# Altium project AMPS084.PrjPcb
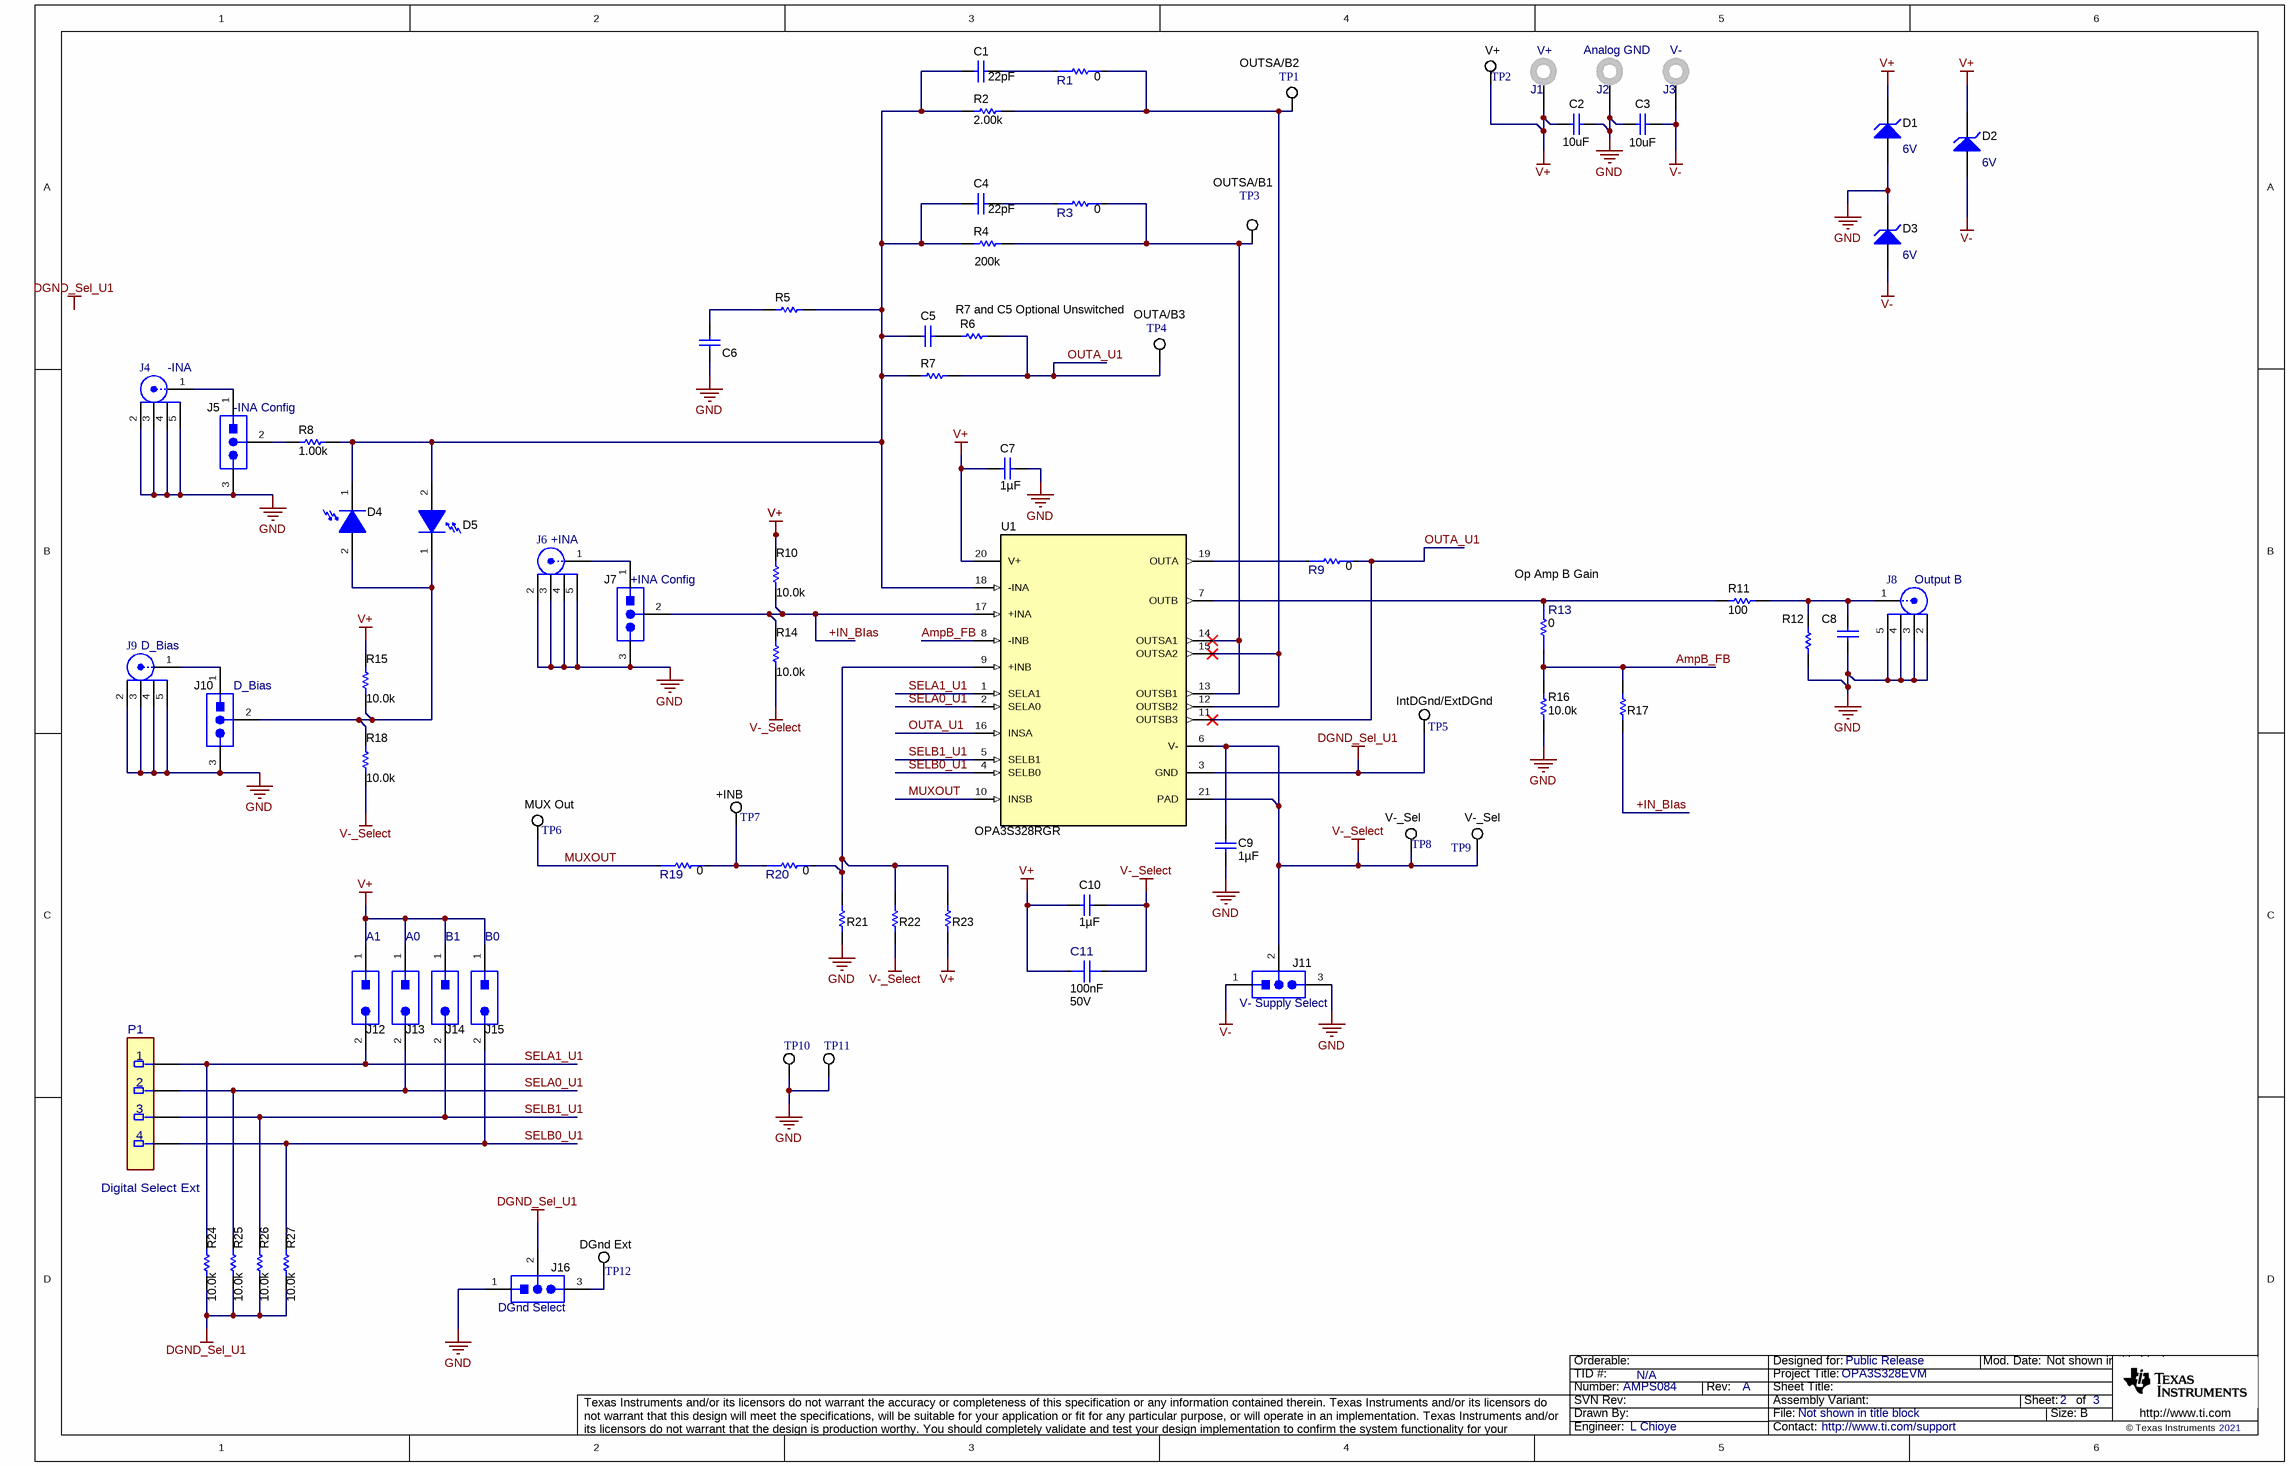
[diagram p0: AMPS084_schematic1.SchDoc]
TID: N/A; TechSupport: http://www.ti.com/support; SCH_Rev: A; PRJ_Title: OPA3S328EVM; PRJ_Number: AMPS084; PRJ_Engineer: L Chioye; PRJ_Customer: Public Release; PCB_Rev: A; PCB_Layout: L Chioye; CopyrightYear: 2021
3 sheets, 183 parts. Net scope: global (net labels, ports and power ports of the same name join across sheets).
Board file: AMPS084.PcbDoc
Sheets:
  AMPS084_schematic1.SchDoc
  AMPS084_schematic2.SchDoc
  AMPS084_Hardware.SchDoc

## Sheet AMPS084_schematic1.SchDoc
size 431 x 279 mm; Date: Not shown in title block; ApprovedBy: Not shown in title block; CheckedBy: Not shown in title block; Author: Not shown in title block; CompanyName: Not shown in title block; Engineer: Not shown in title block; Organization: Not shown in title block; Address1: Not shown in title block; Address2: Not shown in title block; Address3: Not shown in title block; Address4: Not shown in title block; DocumentNumber: 2; Revision: Use project parameter SCH_Rev; SheetNumber: 2; SheetTotal: 3; PageSetup: Record=PageOptions¦CenterHorizontal=True¦CenterVertical=True¦PrintScale=1.00¦XCorrection=1.00¦YCorrection=1.00¦PrintKind=0¦BorderSize=5000000¦LeftOffset=0¦BottomOffset=0¦Orientation=2¦PaperLength=1000¦PaperWidth=1000¦Scale=100¦PaperSource=15¦PrintQuality=600¦MediaType=1¦DitherType=10¦PaperKind=Letter¦PrintScaleMode=1

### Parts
C1  ValueDisplayed: 22pF  [0603]  (hidden comment: 06035A220JAT2A)
C2  ValueDisplayed: 10uF  [1206_190]  (hidden comment: C3216X7R1E106M160AE)
C3  ValueDisplayed: 10uF  [1206_190]  (hidden comment: C3216X7R1E106M160AE)
C4  ValueDisplayed: 22pF  [0603]  (hidden comment: 06035A220JAT2A)
C5  C0603C102J5GACTU  [0603]  (value not drawn)
C6  C0603C102J5GACTU  [0603]  (value not drawn)
C7  Cap_F: 1µF  [0805_HV]  (hidden comment: 08055C105KAT2A)
C8  C1206C104M5RACTU  [1206]  (value not drawn)
C9  Cap_F: 1µF  [0805_HV]  (hidden comment: 08055C105KAT2A)
C10  Cap_F: 1µF  [0805_HV]  (hidden comment: 08055C105KAT2A)
C11  Cap_F: 100nF  VDC_V: 50V  [FP-GCE21BR71H104KA01L_0805-MFG]  (hidden comment: GCE21BR71H104KA01L)
D1  value 6V  [SOD-323]  (hidden comment: MMSZ5233BS-7-F)
D2  value 6V  [SOD-323]  (hidden comment: MMSZ5233BS-7-F)
D3  value 6V  [SOD-323]  (hidden comment: MMSZ5233BS-7-F)
D4  SFH 2701  [SFH_2701]  (value not drawn)
D5  SFH 2701  [SFH_2701]  (value not drawn)
J1  V+  [Keystone_575-4]
J2  Analog GND  [Keystone_575-4]
J3  V-  [Keystone_575-4]
J4  -INA  [TE_5-1814832-1]
J5  -INA Config  [Samtec_TSM-103-01-X-SV]
J6  +INA  [TE_5-1814832-1]
J7  +INA Config  [Samtec_TSM-103-01-X-SV]
J8  Output B  [TE_5-1814832-1]
J9  D_Bias  [TE_5-1814832-1]
J10  D_Bias  [Samtec_TSM-103-01-X-SV]
J11  V- Supply Select  [Samtec_TSM-103-01-X-SV]
J12  A1  [Samtec_TSM-102-01-L-SV]
J13  A0  [Samtec_TSM-102-01-L-SV]
J14  B1  [Samtec_TSM-102-01-L-SV]
J15  B0  [Samtec_TSM-102-01-L-SV]
J16  DGnd Select  [Samtec_TSM-103-01-X-SV]
P1  Digital Select Ext  [FP-TSM-104-01-L-SV-P-TR_HDR4-MFG]
R1  Res_ohm: 0  [FP-ERJ-3GEY0R00V_0603-MFG]  (hidden comment: ERJ-3GEY0R00V)
R2  ValueDisplayed: 2.00k  [0603]  (hidden comment: RG1608P-202-B-T5)
R3  Res_ohm: 0  [FP-ERJ-3GEY0R00V_0603-MFG]  (hidden comment: ERJ-3GEY0R00V)
R4  ValueDisplayed: 200k  [0603]  (hidden comment: RG1608P-204-B-T5)
R5  RG1608P-102-B-T5  [0603]  (value not drawn)
R6  RG1608P-102-B-T5  [0603]  (value not drawn)
R7  RG1608P-102-B-T5  [0603]  (value not drawn)
R8  ValueDisplayed: 1.00k  [0805_HV]  (hidden comment: CRCW08051K00FKEA)
R9  Res_ohm: 0  [FP-ERJ-3GEY0R00V_0603-MFG]  (hidden comment: ERJ-3GEY0R00V)
R10  ValueDisplayed: 10.0k  [0603]  (hidden comment: RCG060310K0FKEA)
R11  ValueDisplayed: 100  [0805_HV]  (hidden comment: CRCW0805100RFKEA)
R12  CRCW120610K0FKEA  [1206]  (value not drawn)
R13  Res_ohm: 0  [FP-ERJ-3GEY0R00V_0603-MFG]  (hidden comment: ERJ-3GEY0R00V)
R14  ValueDisplayed: 10.0k  [0603]  (hidden comment: RCG060310K0FKEA)
R15  ValueDisplayed: 10.0k  [0603]  (hidden comment: RCG060310K0FKEA)
R16  ValueDisplayed: 10.0k  [0603]  (hidden comment: RT0603BRD0710KL)
R17  RG1608P-102-B-T5  [0603]  (value not drawn)
R18  ValueDisplayed: 10.0k  [0603]  (hidden comment: RCG060310K0FKEA)
R19  Res_ohm: 0  [FP-ERJ-3GEY0R00V_0603-MFG]  (hidden comment: ERJ-3GEY0R00V)
R20  Res_ohm: 0  [FP-ERJ-3GEY0R00V_0603-MFG]  (hidden comment: ERJ-3GEY0R00V)
R21  RG1608P-102-B-T5  [0603]  (value not drawn)
R22  RG1608P-102-B-T5  [0603]  (value not drawn)
R23  RG1608P-102-B-T5  [0603]  (value not drawn)
R24  ValueDisplayed: 10.0k  [0603]  (hidden comment: RCG060310K0FKEA)
R25  ValueDisplayed: 10.0k  [0603]  (hidden comment: RCG060310K0FKEA)
R26  ValueDisplayed: 10.0k  [0603]  (hidden comment: RCG060310K0FKEA)
R27  ValueDisplayed: 10.0k  [0603]  (hidden comment: RCG060310K0FKEA)
TP1  OUTSA/B2  [Testpoint_Keystone_Compact]
TP2  V+  [Testpoint_Keystone_Compact]
TP3  OUTSA/B1  [Testpoint_Keystone_Compact]
TP4  OUTA/B3  [Testpoint_Keystone_Compact]
TP5  IntDGnd/ExtDGnd  [Testpoint_Keystone_Compact]
TP6  MUX Out  [Testpoint_Keystone_Compact]
TP7  +INB  [Testpoint_Keystone_Compact]
TP8  V-_Sel  [Testpoint_Keystone_Compact]
TP9  V-_Sel  [Testpoint_Keystone_Compact]
TP10  Analog GND  [Testpoint_Keystone_Compact]  (value not drawn)
TP11  Analog GND  [Testpoint_Keystone_Compact]  (value not drawn)
TP12  DGnd Ext  [Testpoint_Keystone_Compact]
U1  OPA3S328RGR  [RGR0020A]

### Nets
DGND_Sel_U1: J16.2 R24.1 R25.1 R26.1 R27.1 TP5.1 U1.3(GND)
GND: C2.1 C3.2 C6.2 C7.1 C8.1 C9.2 D1.2(A) D3.1(K) J2.1 J4.2 J4.3 J4.4 J4.5 J5.3 J6.2 J6.3 J6.4 J6.5 J7.3 J8.2 J8.3 J8.4 J8.5 J9.2 J9.3 J9.4 J9.5 J10.3 J11.3 J16.1 R12.1 R16.1 R21.1 TP10.1 TP11.1
V+: C2.2 C7.2 C10.2 C11.1 D1.1(K) D2.1(K) J1.1 J12.1 J13.1 J14.1 J15.1 R10.2 R15.2 R23.1 TP2.1 U1.20(V+)
V-: C3.1 D2.2(A) D3.2(A) J3.1 J11.1
V-_Select: C9.1 C10.1 C11.2 J11.2 R14.1 R18.1 R22.1 TP8.1 TP9.1 U1.6(V-) U1.21(PAD)
+IN_BIas: J7.2 R10.1 R14.2 R17.1 U1.17(+INA)
AmpB_FB: R13.1 R16.2 R17.2 U1.8(-INB)
MUXOUT: R19.1 TP6.1 U1.10(INSB)
OUTA_U1: R6.2 R7.2 R9.2 TP4.1 U1.11(OUTSB3) U1.16(INSA)
SELA0_U1: J13.2 P1.2 R25.2 U1.2(SELA0)
SELA1_U1: J12.2 P1.1 R24.2 U1.1(SELA1)
SELB0_U1: J15.2 P1.4 R27.2 U1.4(SELB0)
SELB1_U1: J14.2 P1.3 R26.2 U1.5(SELB1)
NetC1_1: C1.1 R1.1
NetC1_2: C1.2 C4.2 C5.2 D4.1(C) D5.2(A) R2.1 R4.1 R5.2 R7.1 R8.2 U1.18(-INA)
NetC4_1: C4.1 R3.1
NetC5_1: C5.1 R6.1
NetC6_1: C6.1 R5.1
NetC8_2: C8.2 J8.1 R11.2 R12.2
NetD4_2: D4.2(A) D5.1(C) J10.2 R15.1 R18.2
NetJ4_1: J4.1 J5.1
NetJ5_2: J5.2 R8.1
NetJ6_1: J6.1 J7.1
NetJ9_1: J9.1 J10.1
NetJ16_3: J16.3 TP12.1
NetR1_2: R1.2 R2.2 TP1.1 U1.12(OUTSB2) U1.15(OUTSA2)
NetR3_2: R3.2 R4.2 TP3.1 U1.13(OUTSB1) U1.14(OUTSA1)
NetR9_1: R9.1 U1.19(OUTA)
NetR11_1: R11.1 R13.2 U1.7(OUTB)
NetR19_2: R19.2 R20.1 TP7.1
NetR20_2: R20.2 R21.2 R22.2 R23.2 U1.9(+INB)

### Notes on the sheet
- R7 and C5 Optional Unswitched
- (near R13) Op Amp B Gain
- Labels drawn without touching a wire or pin: DGND_Sel_U1

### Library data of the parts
C1 C4 = CMP-0006775-4: CAP, CERM, 22 pF, 50 V, +/- 5%, C0G/NP0, 0603; Manufacturer: AVX; TaMin_C: -55°C; ESR_ohm: 0.259; Polarized: N; SizeAreaWB_mm2: 4.68; Value1: 0.259 ohm; U/M: EA; Value: 22pF; TaMax_C: 125°C; SizeZ_mm: 1; SizeX_mm: 1.6; SizeY_mm: 0.8; Value2: 50V; SizeArea_mm2: 1.28; AEC Category: Q200
C2 C3 = CMP-0008692-1: CAP, CERM, 10 uF, 25 V, +/- 20%, X7R, 1206_190; Manufacturer: TDK; TaMin_C: -55°C; Polarized: N; SizeAreaWB_mm2: 10.92; Value1: Unknown; U/M: EA; Value: 10uF; TaMax_C: 125°C; SizeZ_mm: 1.9; SizeX_mm: 3.2; SizeY_mm: 1.6; Cap_Case: 1206; Value2: 25V; SizeArea_mm2: 5.12; Cap_F: 10µF; AEC Category: Q200
C5 C6 = CMP-0006843-4: CAP, CERM, 1000 pF, 50 V, +/- 5%, C0G/NP0, 0603; Manufacturer: Kemet; TaMin_C: -55°C; Polarized: N; SizeAreaWB_mm2: 4.68; Value1: Unknown; U/M: EA; Value: 1000pF; TaMax_C: 125°C; SizeZ_mm: 1; SizeX_mm: 1.6; SizeY_mm: 0.8; Value2: 50V; SizeArea_mm2: 1.28; Cap_F: 1nF; AEC Category: Q200
C7 C9 C10 = CMP-0007634-2: CAP, CERM, 1 uF, 50 V, +/- 10%, X7R, 0805; Manufacturer: AVX; TaMin_C: -55°C; Polarized: N; SizeAreaWB_mm2: 6.75; Value1: Unknown; U/M: EA; Value: 1uF; TaMax_C: 125°C; SizeZ_mm: 1.45; SizeX_mm: 2; SizeY_mm: 1.25; Cap_Case: 0805; Value2: 50V; SizeArea_mm2: 2.5; AEC Category: Q200
C8 = CMP-0008587-2: CAP, CERM, 0.1 uF, 50 V, +/- 20%, X7R, 1206; Manufacturer: Kemet; TaMin_C: -55°C; ESR_ohm: 0.059; Polarized: N; SizeAreaWB_mm2: 10.92; Value1: 0.059 ohm; U/M: EA; Value: 0.1uF; TaMax_C: 125°C; SizeZ_mm: 1.35; SizeX_mm: 3.2; SizeY_mm: 1.6; Value2: 50V; SizeArea_mm2: 5.12; Cap_F: 100nF; IRMS_A: 1.2A; AEC Category: Q200
C11 = CMP-0088731-1: 0.1µF ±10% 50V Ceramic Capacitor X7R 0805 (2012 Metric); Manufacturer: Murata; SizeZ_mm: 1.45mm; TempCo: 15%; AEC Grade: Grade 1; AEC Qualified: Yes; ValueDisplayed: 0.1uF
D1-D3 = CMP-0005856-3: Diode, Zener, 6 V, 200 mW, SOD-323; Manufacturer: Diodes Inc.; Power_W: 200mW; SizeY_mm: 1.35; SizeArea_mm2: 3.645; AEC Category: Q101; RJA_CperW: 350; SizeZ_mm: 1; Value1: 0.2W; SizeX_mm: 2.7; SizeAreaWB_mm2: 8.695
D4 D5 = CMP-0002013-4: High Speed PIN Photodiode, SMD; Manufacturer: OSRAM; Value: 820nm
J1-J3 = CMP-0055165-1: Standard Banana Jack, Uninsulated, 5.5mm; Manufacturer: Keystone; PartNumber: 575-4; CT: TRUE; Green_REACh: Passed; CNHeader: FALSE; Green_Lifecycle: Active
J4 J6 J8 J9 = CMP-0054990-1: SMA Straight PCB Socket Die Cast, 50 Ohm, TH; Manufacturer: TE Connectivity; PartNumber: 5-1814832-1; CNHeader: FALSE; Green_Lifecycle: Active; Green_REACh: Passed; CT: TRUE
J5 J7 J10 J11 J16 = CMP-0075402-1: Header, 100mil, 3x1, Gold, SMT; PartNumber: TSM-103-01-L-SV; Manufacturer: Samtec; Green_REACh: Passed; CT: False; Green_Lifecycle: Active; CNHeader: True
J12-J15 = CMP-0075467-1: Header, 100mil, 2x1, Gold with Tin Tail, SMT; PartNumber: TSM-102-01-L-SV; Manufacturer: Samtec; Pitch_mm: 2.54; Gender: Male; Cert_CSA: Y; Green_REACh: Passed; Current_A: 5.4A; Voltage_V: 475V; CT: False; Shrouded: N; Green_Lifecycle: Active; Row_Count: 1; CNHeader: True
P1 = CMP-0087359-1: PartNumber: TSM-104-01-L-SV-P-TR; Manufacturer: Samtec; ContactFinish: Gold,Nickel; Current_A: 5.4A; Voltage_V: 475V; Row_Count: 1
R1 R3 R9 R13 R19 R20 = CMP-0089143-1: 0 Ohms Jumper 0.1W, 1/10W Chip Resistor 0603 (1608 Metric) Automotive AEC-Q200 Thick Film; Manufacturer: Panasonic; SizeZ_mm: 0.55mm; AEC Grade: Grade 0; VDC_V: 75V; TempCo: -100/+600ppm/°C; AEC Qualified: Yes; Power_W: 100mW; Tolerance_%: 5%
R2 = CMP-0023463-3: RES, 2.00 k, 0.1%, 0.1 W, 0603; Manufacturer: Susumu Co Ltd; Power_W: 100mW; TempCo: 25 ppm/C; Value_Code: 2k00; U/M: EA; Value: 2.00k; EIA_Code: E192; Res_ohm: 2k; SizeX_mm: 1.6; SizeY_mm: 0.8; SizeZ_mm: 1; Value2: 0.1W; SizeArea_mm2: 1.28; VDC_V: 75V; AEC Category: Q200
R4 = CMP-0023465-3: RES, 200 k, 0.1%, 0.1 W, 0603; Manufacturer: Susumu Co Ltd; Power_W: 100mW; TempCo: 25 ppm/C; U/M: EA; Value: 200k; EIA_Code: E192; SizeX_mm: 1.6; SizeY_mm: 0.8; SizeZ_mm: 1; Value2: 0.1W; SizeArea_mm2: 1.28; VDC_V: 75V; AEC Category: Q200
R5-R7 R17 R21-R23 = CMP-0023403-3: RES, 1.00 k, 0.1%, 0.1 W, 0603; Manufacturer: Susumu Co Ltd; Power_W: 100mW; TempCo: 25 ppm/C; Value_Code: 1k00; U/M: EA; Value: 1.00k; EIA_Code: E192; Res_ohm: 1k; SizeX_mm: 1.6; SizeY_mm: 0.8; SizeZ_mm: 1; Value2: 0.1W; SizeArea_mm2: 1.28; VDC_V: 75V; AEC Category: Q200
R8 = CMP-0020951-3: RES, 1.00 k, 1%, 0.125 W, AEC-Q200 Grade 0, 0805; Manufacturer: Vishay-Dale; Power_W: 125mW; TempCo: 100 ppm/C; Value_Code: 1k00; Value: 1.00k; EIA_Code: E96; Res_ohm: 1k; SizeX_mm: 2; SizeY_mm: 1.25; SizeZ_mm: 1.45; Value2: 0.125W; SizeArea_mm2: 2.5; AEC Qualified: Y; VDC_V: 150V; AEC Category: Q200; AEC Grade: 0
R10 R14 R15 R18 R24-R27 = CMP-0023337-3: RES, 10.0 k, 1%, 0.1 W, 0603; Manufacturer: Vishay Draloric; Power_W: 100mW; TempCo: 100 ppm/C; Value_Code: 10k0; U/M: EA; Value: 10.0k; EIA_Code: E96; Res_ohm: 10k; SizeX_mm: 1.6; SizeY_mm: 0.8; SizeZ_mm: 1; Value2: 0.1W; SizeArea_mm2: 1.28; AEC Qualified: N; VDC_V: 75V; AEC Category: Q200
R11 = CMP-0020835-3: RES, 100, 1%, 0.125 W, AEC-Q200 Grade 0, 0805; Manufacturer: Vishay-Dale; Power_W: 125mW; TempCo: 100 ppm/C; Value_Code: 100R; Value: 100; EIA_Code: E96; SizeX_mm: 2; SizeY_mm: 1.25; SizeZ_mm: 1.45; Value2: 0.125W; SizeArea_mm2: 2.5; AEC Qualified: Y; VDC_V: 150V; AEC Category: Q200; AEC Grade: 0
R12 = CMP-0016577-1: RES, 10.0 k, 1%, 0.25 W, 1206; Manufacturer: Vishay-Dale; Power_W: 250mW; TempCo: 100 ppm/C; Value_Code: 10k0; U/M: EA; Value: 10.0k; EIA_Code: E96; Res_ohm: 10k; SizeX_mm: 3.2; SizeY_mm: 1.6; SizeZ_mm: 1.35; Value2: 0.25W; SizeArea_mm2: 5.12; VDC_V: 200V; AEC Category: Q200
R16 = CMP-0023653-3: RES, 10.0 k, 0.1%, 0.1 W, 0603; Manufacturer: Yageo America; Power_W: 100mW; TempCo: 25 ppm/C; Value_Code: 10k0; U/M: EA; Value: 10.0k; EIA_Code: E192; Res_ohm: 10k; SizeX_mm: 1.6; SizeY_mm: 0.8; SizeZ_mm: 1; Value2: 0.1W; SizeArea_mm2: 1.28; VDC_V: 75V; AEC Category: Q200
TP1-TP12 = CMP-0055153-1: Test Point, Compact, SMT; Manufacturer: Keystone; CNHeader: FALSE; Green_Lifecycle: Active; Green_REACh: Passed; CT: TRUE
U1 = CMP-0860039-1: 40-MHz CMOS Operational Amplifier With Switches, RGR0020A (VQFN-20); Manufacturer: Texas Instruments; SizeArea_mm2: 12.25; CompType: IC; AEC Category: Q200; SizeZ_mm: 1; SizeAreaWB_mm2: 20.25; AEC Qualified: N; SizeX_mm: 3.5

## Sheet AMPS084_schematic2.SchDoc
size 431 x 279 mm; Date: Not shown in title block; ApprovedBy: Not shown in title block; CheckedBy: Not shown in title block; Author: Not shown in title block; CompanyName: Not shown in title block; Engineer: Not shown in title block; Organization: Not shown in title block; Address1: Not shown in title block; Address2: Not shown in title block; Address3: Not shown in title block; Address4: Not shown in title block; DocumentNumber: 2; Revision: Use project parameter SCH_Rev; SheetNumber: 2; SheetTotal: 3; PageSetup: Record=PageOptions¦CenterHorizontal=True¦CenterVertical=True¦PrintScale=1.00¦XCorrection=1.00¦YCorrection=1.00¦PrintKind=0¦BorderSize=5000000¦LeftOffset=0¦BottomOffset=0¦Orientation=2¦PaperLength=1000¦PaperWidth=1000¦Scale=100¦PaperSource=15¦PrintQuality=600¦MediaType=1¦DitherType=10¦PaperKind=Letter¦PrintScaleMode=1
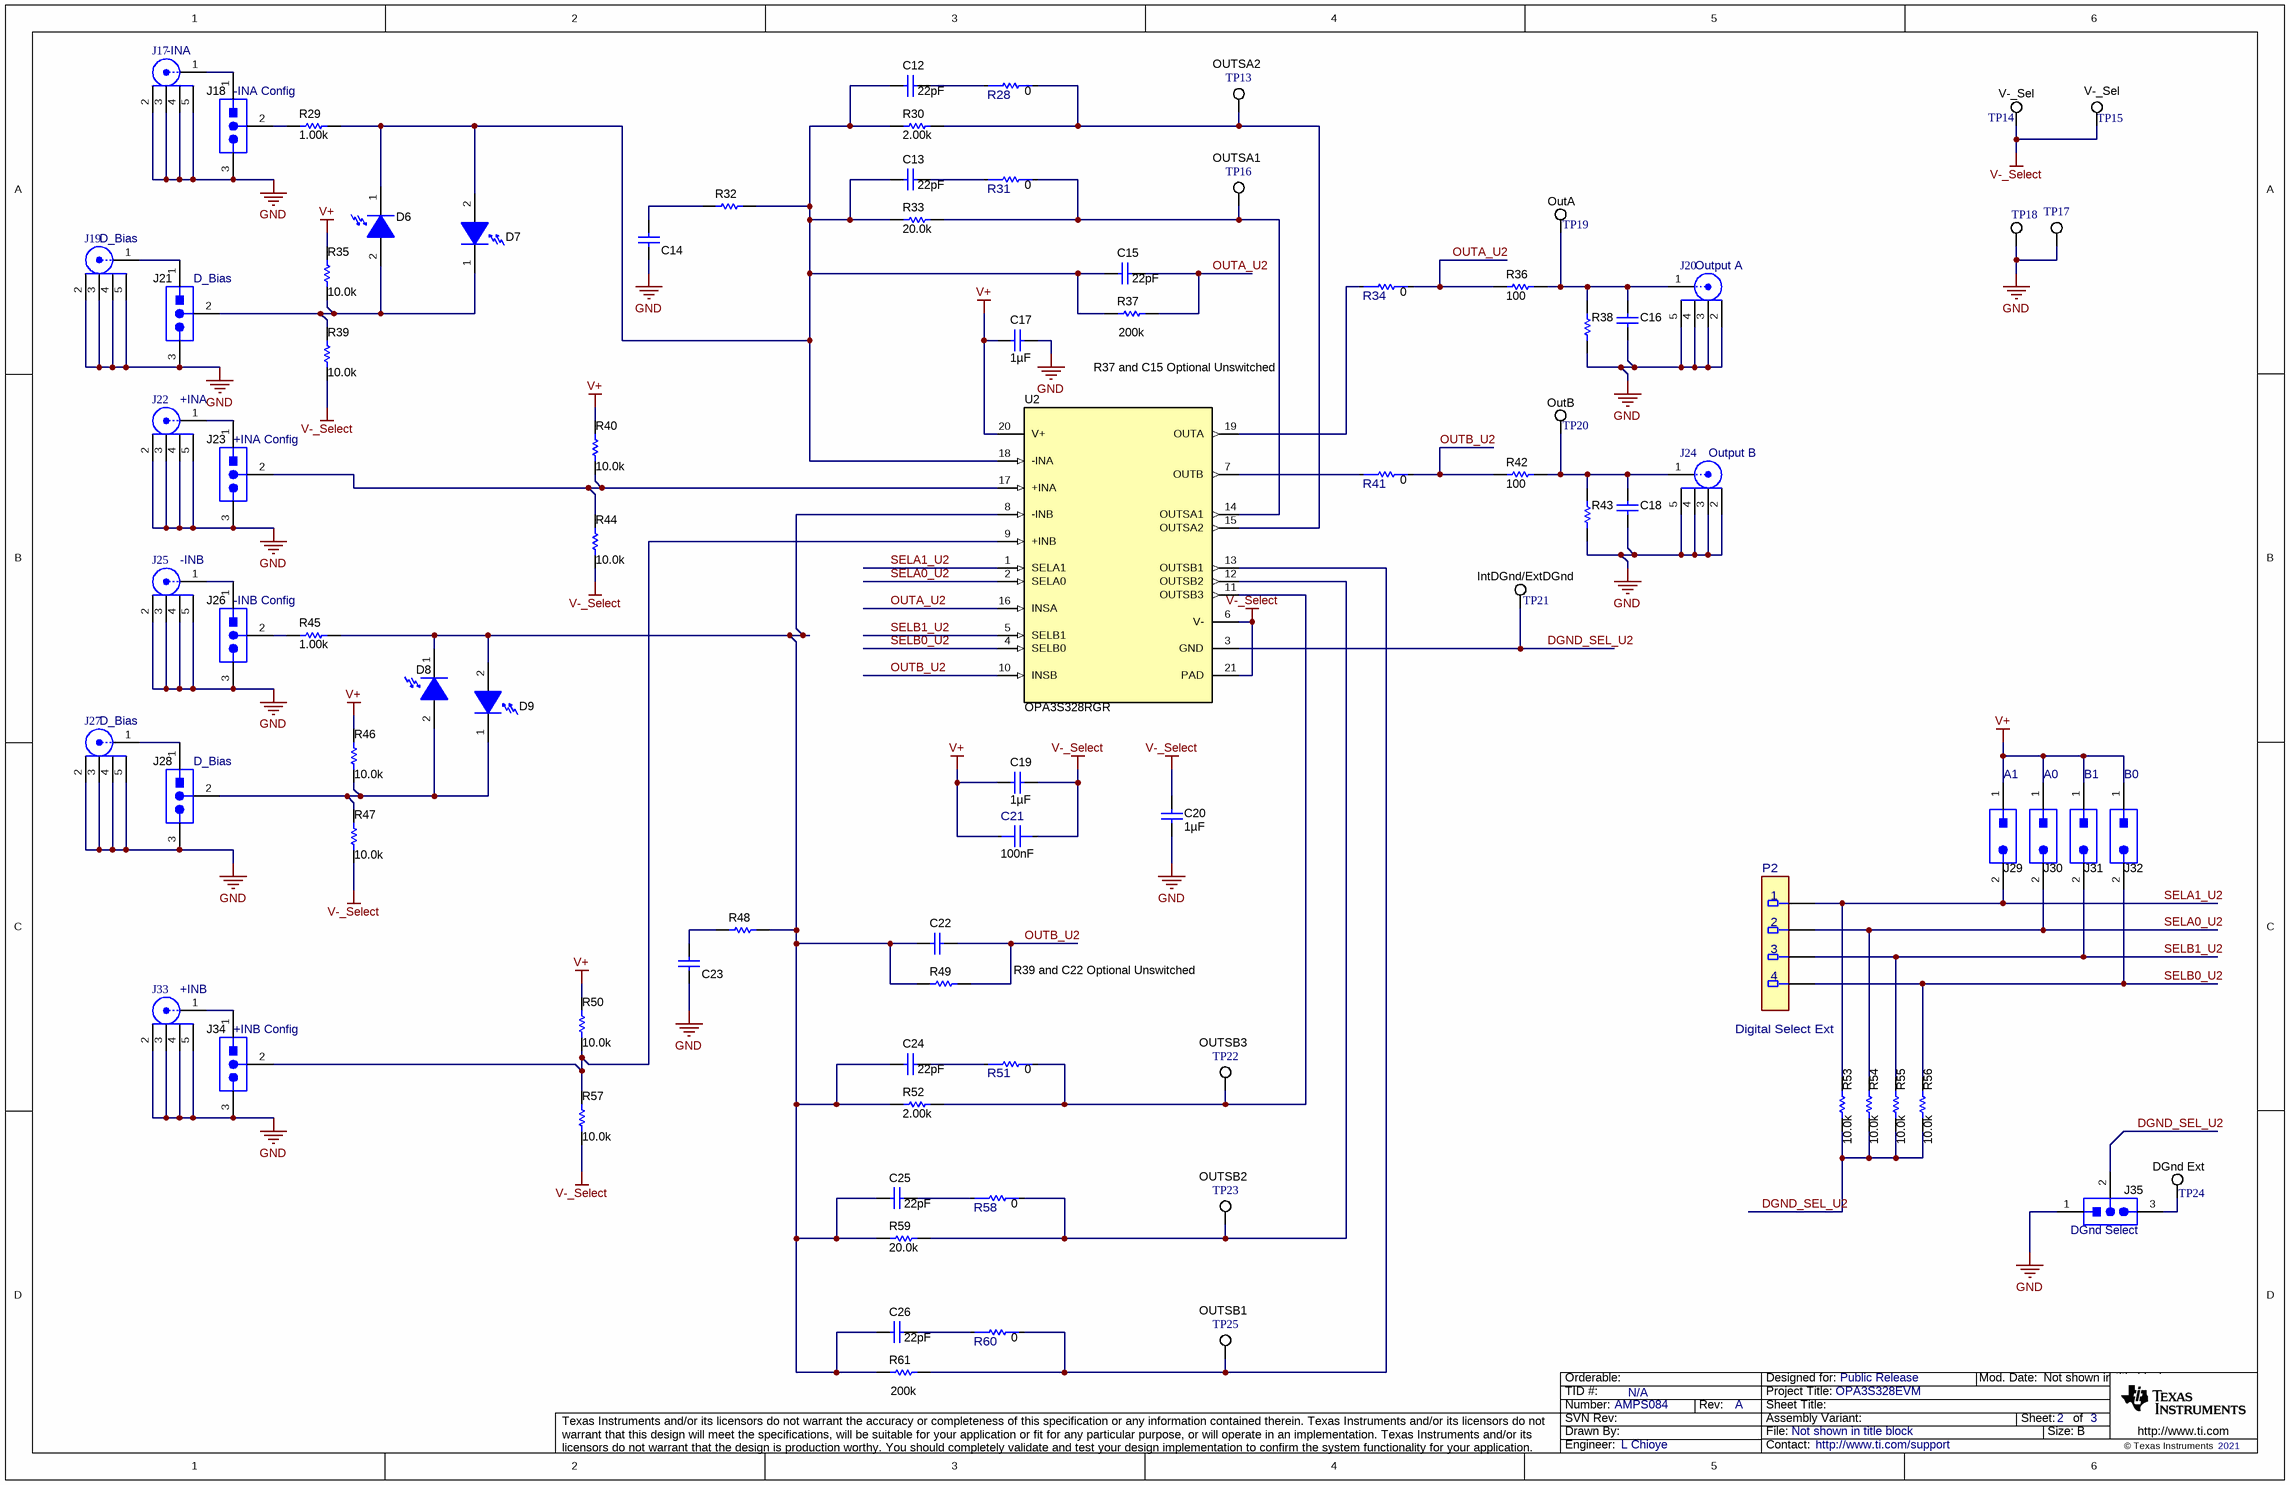
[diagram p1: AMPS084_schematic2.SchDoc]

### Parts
C12  ValueDisplayed: 22pF  [0603]  (hidden comment: 06035A220JAT2A)
C13  ValueDisplayed: 22pF  [0603]  (hidden comment: 06035A220JAT2A)
C14  C0603C102J5GACTU  [0603]  (value not drawn)
C15  ValueDisplayed: 22pF  [0603]  (hidden comment: 06035A220JAT2A)
C16  C1206C104M5RACTU  [1206]  (value not drawn)
C17  Cap_F: 1µF  [0805_HV]  (hidden comment: 08055C105KAT2A)
C18  C1206C104M5RACTU  [1206]  (value not drawn)
C19  Cap_F: 1µF  [0805_HV]  (hidden comment: 08055C105KAT2A)
C20  Cap_F: 1µF  [0805_HV]  (hidden comment: 08055C105KAT2A)
C21  Cap_F: 100nF  [FP-GCE21BR71H104KA01L_0805-MFG]  (hidden comment: GCE21BR71H104KA01L)
C22  C0603C102J5GACTU  [0603]  (value not drawn)
C23  C0603C102J5GACTU  [0603]  (value not drawn)
C24  ValueDisplayed: 22pF  [0603]  (hidden comment: 06035A220JAT2A)
C25  ValueDisplayed: 22pF  [0603]  (hidden comment: 06035A220JAT2A)
C26  ValueDisplayed: 22pF  [0603]  (hidden comment: 06035A220JAT2A)
D6  SFH 2701  [SFH_2701]  (value not drawn)
D7  SFH 2701  [SFH_2701]  (value not drawn)
D8  SFH 2701  [SFH_2701]  (value not drawn)
D9  SFH 2701  [SFH_2701]  (value not drawn)
J17  -INA  [TE_5-1814832-1]
J18  -INA Config  [Samtec_TSM-103-01-X-SV]
J19  D_Bias  [TE_5-1814832-1]
J20  Output A  [TE_5-1814832-1]
J21  D_Bias  [Samtec_TSM-103-01-X-SV]
J22  +INA  [TE_5-1814832-1]
J23  +INA Config  [Samtec_TSM-103-01-X-SV]
J24  Output B  [TE_5-1814832-1]
J25  -INB  [TE_5-1814832-1]
J26  -INB Config  [Samtec_TSM-103-01-X-SV]
J27  D_Bias  [TE_5-1814832-1]
J28  D_Bias  [Samtec_TSM-103-01-X-SV]
J29  A1  [Samtec_TSM-102-01-L-SV]
J30  A0  [Samtec_TSM-102-01-L-SV]
J31  B1  [Samtec_TSM-102-01-L-SV]
J32  B0  [Samtec_TSM-102-01-L-SV]
J33  +INB  [TE_5-1814832-1]
J34  +INB Config  [Samtec_TSM-103-01-X-SV]
J35  DGnd Select  [Samtec_TSM-103-01-X-SV]
P2  Digital Select Ext  [FP-TSM-104-01-L-SV-P-TR_HDR4-MFG]
R28  Res_ohm: 0  [FP-ERJ-3GEY0R00V_0603-MFG]  (hidden comment: ERJ-3GEY0R00V)
R29  ValueDisplayed: 1.00k  [0805_HV]  (hidden comment: CRCW08051K00FKEA)
R30  ValueDisplayed: 2.00k  [0603]  (hidden comment: RG1608P-202-B-T5)
R31  Res_ohm: 0  [FP-ERJ-3GEY0R00V_0603-MFG]  (hidden comment: ERJ-3GEY0R00V)
R32  RG1608P-102-B-T5  [0603]  (value not drawn)
R33  ValueDisplayed: 20.0k  [0603]  (hidden comment: RG1608P-203-B-T5)
R34  Res_ohm: 0  [FP-ERJ-3GEY0R00V_0603-MFG]  (hidden comment: ERJ-3GEY0R00V)
R35  ValueDisplayed: 10.0k  [0603]  (hidden comment: RCG060310K0FKEA)
R36  ValueDisplayed: 100  [0805_HV]  (hidden comment: CRCW0805100RFKEA)
R37  ValueDisplayed: 200k  [0603]  (hidden comment: RG1608P-204-B-T5)
R38  CRCW120610K0FKEA  [1206]  (value not drawn)
R39  ValueDisplayed: 10.0k  [0603]  (hidden comment: RCG060310K0FKEA)
R40  ValueDisplayed: 10.0k  [0603]  (hidden comment: RCG060310K0FKEA)
R41  Res_ohm: 0  [FP-ERJ-3GEY0R00V_0603-MFG]  (hidden comment: ERJ-3GEY0R00V)
R42  ValueDisplayed: 100  [0805_HV]  (hidden comment: CRCW0805100RFKEA)
R43  CRCW120610K0FKEA  [1206]  (value not drawn)
R44  ValueDisplayed: 10.0k  [0603]  (hidden comment: RCG060310K0FKEA)
R45  ValueDisplayed: 1.00k  [0805_HV]  (hidden comment: CRCW08051K00FKEA)
R46  ValueDisplayed: 10.0k  [0603]  (hidden comment: RCG060310K0FKEA)
R47  ValueDisplayed: 10.0k  [0603]  (hidden comment: RCG060310K0FKEA)
R48  RG1608P-102-B-T5  [0603]  (value not drawn)
R49  RG1608P-102-B-T5  [0603]  (value not drawn)
R50  ValueDisplayed: 10.0k  [0603]  (hidden comment: RCG060310K0FKEA)
R51  Res_ohm: 0  [FP-ERJ-3GEY0R00V_0603-MFG]  (hidden comment: ERJ-3GEY0R00V)
R52  ValueDisplayed: 2.00k  [0603]  (hidden comment: RG1608P-202-B-T5)
R53  ValueDisplayed: 10.0k  [0603]  (hidden comment: RCG060310K0FKEA)
R54  ValueDisplayed: 10.0k  [0603]  (hidden comment: RCG060310K0FKEA)
R55  ValueDisplayed: 10.0k  [0603]  (hidden comment: RCG060310K0FKEA)
R56  ValueDisplayed: 10.0k  [0603]  (hidden comment: RCG060310K0FKEA)
R57  ValueDisplayed: 10.0k  [0603]  (hidden comment: RCG060310K0FKEA)
R58  Res_ohm: 0  [FP-ERJ-3GEY0R00V_0603-MFG]  (hidden comment: ERJ-3GEY0R00V)
R59  ValueDisplayed: 20.0k  [0603]  (hidden comment: RG1608P-203-B-T5)
R60  Res_ohm: 0  [FP-ERJ-3GEY0R00V_0603-MFG]  (hidden comment: ERJ-3GEY0R00V)
R61  ValueDisplayed: 200k  [0603]  (hidden comment: RG1608P-204-B-T5)
TP13  OUTSA2  [Testpoint_Keystone_Compact]
TP14  V-_Sel  [Testpoint_Keystone_Compact]
TP15  V-_Sel  [Testpoint_Keystone_Compact]
TP16  OUTSA1  [Testpoint_Keystone_Compact]
TP17  Analog GND  [Testpoint_Keystone_Compact]  (value not drawn)
TP18  Analog GND  [Testpoint_Keystone_Compact]  (value not drawn)
TP19  OutA  [Testpoint_Keystone_Compact]
TP20  OutB  [Testpoint_Keystone_Compact]
TP21  IntDGnd/ExtDGnd  [Testpoint_Keystone_Compact]
TP22  OUTSB3  [Testpoint_Keystone_Compact]
TP23  OUTSB2  [Testpoint_Keystone_Compact]
TP24  DGnd Ext  [Testpoint_Keystone_Compact]
TP25  OUTSB1  [Testpoint_Keystone_Compact]
U2  OPA3S328RGR  [RGR0020A]

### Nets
GND: C14.2 C16.1 C17.1 C18.1 C20.2 C23.2 J17.2 J17.3 J17.4 J17.5 J18.3 J19.2 J19.3 J19.4 J19.5 J20.2 J20.3 J20.4 J20.5 J21.3 J22.2 J22.3 J22.4 J22.5 J23.3 J24.2 J24.3 J24.4 J24.5 J25.2 J25.3 J25.4 J25.5 J26.3 J27.2 J27.3 J27.4 J27.5 J28.3 J33.2 J33.3 J33.4 J33.5 J34.3 J35.1 R38.1 R43.1 TP17.1 TP18.1
V+: C17.2 C19.2 C21.1 J29.1 J30.1 J31.1 J32.1 R35.2 R40.2 R46.2 R50.2 U2.20(V+)
V-_Select: C19.1 C20.1 C21.2 R39.1 R44.1 R47.1 R57.1 TP14.1 TP15.1 U2.6(V-) U2.21(PAD)
DGND_SEL_U2: J35.2 R53.1 R54.1 R55.1 R56.1 TP21.1 U2.3(GND)
OUTA_U2: C15.1 R34.2 R36.1 R37.2 U2.16(INSA)
OUTB_U2: C22.1 R41.2 R42.1 R49.2 U2.10(INSB)
SELA0_U2: J30.2 P2.2 R54.2 U2.2(SELA0)
SELA1_U2: J29.2 P2.1 R53.2 U2.1(SELA1)
SELB0_U2: J32.2 P2.4 R56.2 U2.4(SELB0)
SELB1_U2: J31.2 P2.3 R55.2 U2.5(SELB1)
NetC12_1: C12.1 R28.1
NetC12_2: C12.2 C13.2 C15.2 D6.1(C) D7.2(A) R29.2 R30.1 R32.2 R33.1 R37.1 U2.18(-INA)
NetC13_1: C13.1 R31.1
NetC14_1: C14.1 R32.1
NetC16_2: C16.2 J20.1 R36.2 R38.2 TP19.1
NetC18_2: C18.2 J24.1 R42.2 R43.2 TP20.1
NetC22_2: C22.2 C24.2 C25.2 C26.2 D8.1(C) D9.2(A) R45.2 R48.2 R49.1 R52.1 R59.1 R61.1 U2.8(-INB)
NetC23_1: C23.1 R48.1
NetC24_1: C24.1 R51.1
NetC25_1: C25.1 R58.1
NetC26_1: C26.1 R60.1
NetD6_2: D6.2(A) D7.1(C) J21.2 R35.1 R39.2
NetD8_2: D8.2(A) D9.1(C) J28.2 R46.1 R47.2
NetJ17_1: J17.1 J18.1
NetJ18_2: J18.2 R29.1
NetJ19_1: J19.1 J21.1
NetJ22_1: J22.1 J23.1
NetJ23_2: J23.2 R40.1 R44.2 U2.17(+INA)
NetJ25_1: J25.1 J26.1
NetJ26_2: J26.2 R45.1
NetJ27_1: J27.1 J28.1
NetJ33_1: J33.1 J34.1
NetJ34_2: J34.2 R50.1 R57.2 U2.9(+INB)
NetJ35_3: J35.3 TP24.1
NetR28_2: R28.2 R30.2 TP13.1 U2.15(OUTSA2)
NetR31_2: R31.2 R33.2 TP16.1 U2.14(OUTSA1)
NetR34_1: R34.1 U2.19(OUTA)
NetR41_1: R41.1 U2.7(OUTB)
NetR51_2: R51.2 R52.2 TP22.1 U2.11(OUTSB3)
NetR58_2: R58.2 R59.2 TP23.1 U2.12(OUTSB2)
NetR60_2: R60.2 R61.2 TP25.1 U2.13(OUTSB1)

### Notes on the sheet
- R37 and C15 Optional Unswitched
- R39 and C22 Optional Unswitched

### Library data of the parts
C12 C13 C15 C24-C26 = CMP-0006775-4: as C1 on sheet AMPS084_schematic1
C14 C22 C23 = CMP-0006843-4: as C5 on sheet AMPS084_schematic1
C16 C18 = CMP-0008587-2: as C8 on sheet AMPS084_schematic1
C17 C19 C20 = CMP-0007634-2: as C7 on sheet AMPS084_schematic1
C21 = CMP-0088731-1: as C11 on sheet AMPS084_schematic1
D6-D9 = CMP-0002013-4: as D4 on sheet AMPS084_schematic1
J17 J19 J20 J22 J24 J25 J27 J33 = CMP-0054990-1: as J4 on sheet AMPS084_schematic1
J18 J21 J23 J26 J28 J34 J35 = CMP-0075402-1: as J5 on sheet AMPS084_schematic1
J29-J32 = CMP-0075467-1: as J12 on sheet AMPS084_schematic1
P2 = CMP-0087359-1: as P1 on sheet AMPS084_schematic1
R28 R31 R34 R41 R51 R58 R60 = CMP-0089143-1: as R1 on sheet AMPS084_schematic1
R29 R45 = CMP-0020951-3: as R8 on sheet AMPS084_schematic1
R30 R52 = CMP-0023463-3: as R2 on sheet AMPS084_schematic1
R32 R48 R49 = CMP-0023403-3: as R5 on sheet AMPS084_schematic1
R33 R59 = CMP-0023464-3: RES, 20.0 k, 0.1%, 0.1 W, 0603; Manufacturer: Susumu Co Ltd; Power_W: 100mW; TempCo: 25 ppm/C; Value_Code: 20k0; U/M: EA; Value: 20.0k; EIA_Code: E192; Res_ohm: 20k; SizeX_mm: 1.6; SizeY_mm: 0.8; SizeZ_mm: 1; Value2: 0.1W; SizeArea_mm2: 1.28; VDC_V: 75V; AEC Category: Q200
R35 R39 R40 R44 R46 R47 R50 R53-R57 = CMP-0023337-3: as R10 on sheet AMPS084_schematic1
R36 R42 = CMP-0020835-3: as R11 on sheet AMPS084_schematic1
R37 R61 = CMP-0023465-3: as R4 on sheet AMPS084_schematic1
R38 R43 = CMP-0016577-1: as R12 on sheet AMPS084_schematic1
TP13-TP25 = CMP-0055153-1: as TP1 on sheet AMPS084_schematic1
U2 = CMP-0860039-1: as U1 on sheet AMPS084_schematic1

## Sheet AMPS084_Hardware.SchDoc
size 431 x 279 mm; Date: Not shown in title block; ApprovedBy: Not shown in title block; CheckedBy: Not shown in title block; Author: Not shown in title block; CompanyName: Not shown in title block; Engineer: Not shown in title block; Organization: Not shown in title block; Address1: Not shown in title block; Address2: Not shown in title block; Address3: Not shown in title block; Address4: Not shown in title block; DocumentNumber: 3; Revision: Use project parameter SCH_Rev; SheetNumber: 3; SheetTotal: 3; PageSetup: Record=PageOptions¦CenterHorizontal=True¦CenterVertical=True¦PrintScale=1.00¦XCorrection=1.00¦YCorrection=1.00¦PrintKind=0¦BorderSize=5000000¦LeftOffset=0¦BottomOffset=0¦Orientation=2¦PaperLength=1000¦PaperWidth=1000¦Scale=100¦PaperSource=15¦PrintQuality=600¦MediaType=1¦DitherType=10¦PaperKind=Letter¦PrintScaleMode=1
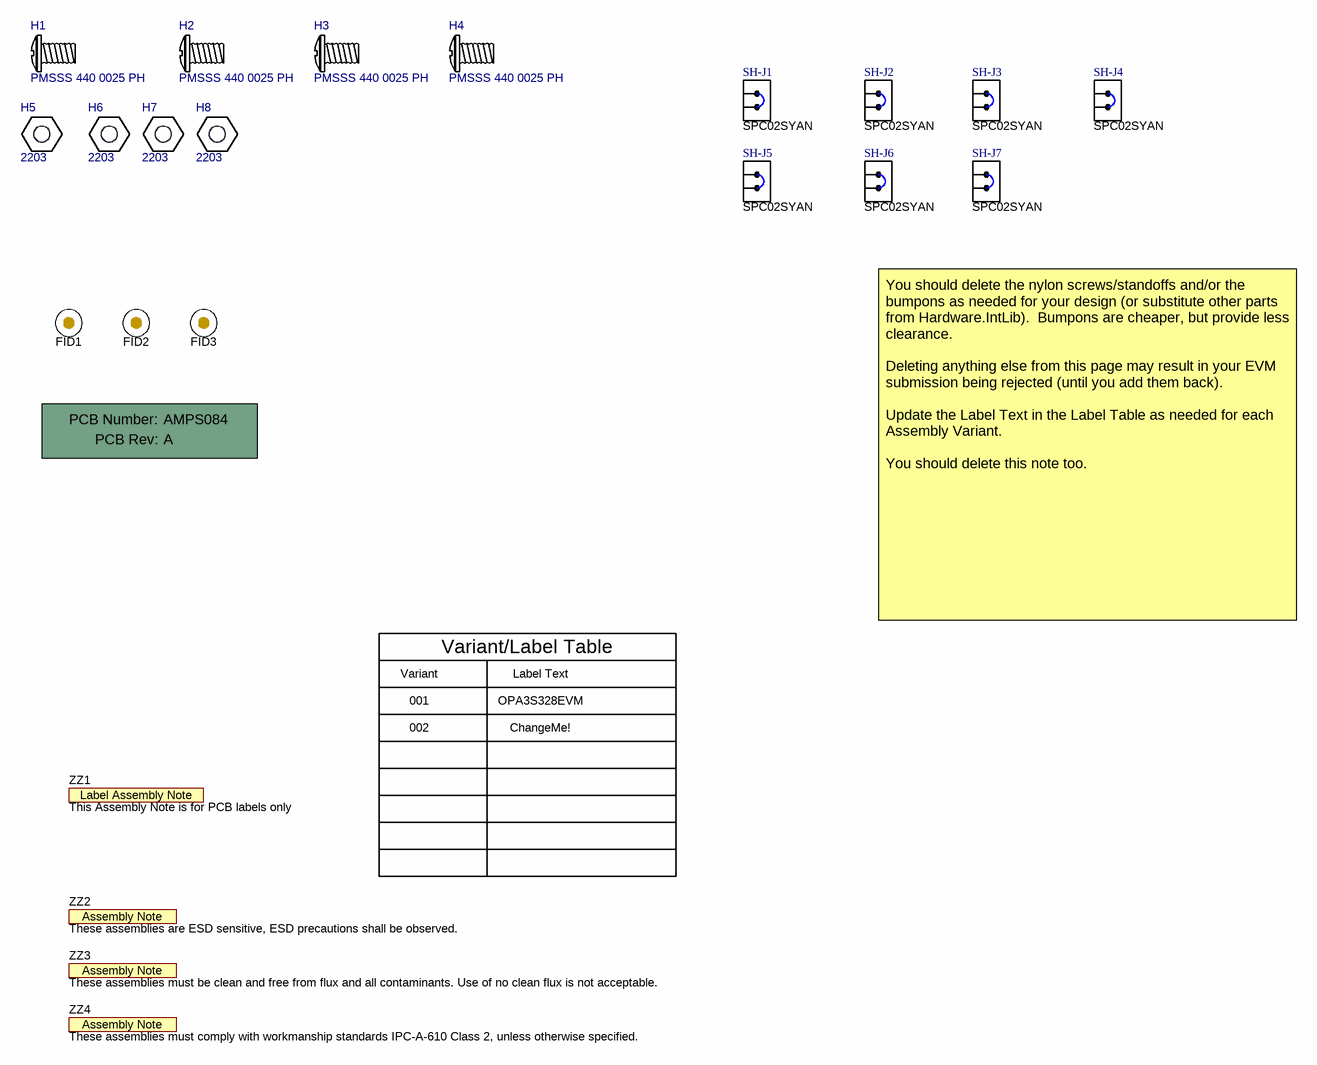
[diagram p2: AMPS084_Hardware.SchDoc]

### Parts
!PCB1  Printed Circuit Board  (value not drawn)  (mechanical)
FID1  Fiducial  [Fiducial10-20]  (value not drawn)
FID2  Fiducial  [Fiducial10-20]  (value not drawn)
FID3  Fiducial  [Fiducial10-20]  (value not drawn)
H1  PMSSS 440 0025 PH  [B_F_PMSSS4400025PH]
H2  PMSSS 440 0025 PH  [B_F_PMSSS4400025PH]
H3  PMSSS 440 0025 PH  [B_F_PMSSS4400025PH]
H4  PMSSS 440 0025 PH  [B_F_PMSSS4400025PH]
H5  2203  [Keystone_2203]
H6  2203  [Keystone_2203]
H7  2203  [Keystone_2203]
H8  2203  [Keystone_2203]
SH-J1  SPC02SYAN  [SPC02SYAN]  (mechanical)
SH-J2  SPC02SYAN  [SPC02SYAN]  (mechanical)
SH-J3  SPC02SYAN  [SPC02SYAN]  (mechanical)
SH-J4  SPC02SYAN  [SPC02SYAN]  (mechanical)
SH-J5  SPC02SYAN  [SPC02SYAN]  (mechanical)
SH-J6  SPC02SYAN  [SPC02SYAN]  (mechanical)
SH-J7  SPC02SYAN  [SPC02SYAN]  (mechanical)
ZZ1  This Assembly Note is for PCB labels only  [AssemblyNoteLabel]  (no BOM)
ZZ2  These assemblies are ESD sensitive, ESD precautions shall be observed.  [AssemblyNote]  (no BOM)
ZZ3  These assemblies must be clean and free from flux and all contaminants. Use of no clean flux is not acceptable.  [AssemblyNote]  (no BOM)
ZZ4  These assemblies must comply with workmanship standards IPC-A-610 Class 2, unless otherwise specified.  [AssemblyNote]  (no BOM)

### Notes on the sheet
- Variant
- Variant/Label Table
- Label Text
- You should delete the nylon screws/standoffs and/or the bumpons as needed for your design (or substitute other parts from Hardware.IntLib).  Bumpons are cheaper, but provide less clearance.
  Deleting anything else from this page may result in your EVM submission being rejected (until you add them back).
  Update the Label Text in the Label Table as needed for each Assembly Variant.
  You should delete this note too.
- 001
- 002
- OPA3S328EVM
- ChangeMe!

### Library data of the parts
!PCB1 = CMP-0003618-2: Manufacturer: Any; PartNumber: AMPS084
FID1-FID3 = CMP-0077181-1: Fiducial mark.  There is nothing to buy or mount.
H1-H4 = CMP-0003715-1: MACHINE SCREW PAN PHILLIPS 4-40; Manufacturer: B&F Fastener Supply; CompType: Standoff
H5-H8 = CMP-0003779-1: Manufacturer: Keystone; CompType: Standoff
SH-J1-SH-J7 = CMP-0003642-1: Shunt, 100mil, Flash Gold, Black; Manufacturer: Sullins Connector Solutions; Value: 1x2
ZZ1 = CMP-0003616-3
ZZ2 = CMP-0077236-1
ZZ3 = CMP-0077237-1
ZZ4 = CMP-0077238-1

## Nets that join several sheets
GND: AMPS084_schematic1 (35 pins), AMPS084_schematic2 (49 pins)
V+: AMPS084_schematic1 (16 pins), AMPS084_schematic2 (12 pins)
V-_Select: AMPS084_schematic1 (11 pins), AMPS084_schematic2 (11 pins)

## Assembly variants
001: not fitted C5 C6 C8 C14 C16 C18 C22 C23 D4 D5 D6 D7 D8 D9 FID1 FID2 FID3 J9 J19 J27 R5 R6 R7 R12 R16 R17 R21 R22 R23 R32 R38 R43 R48 R49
